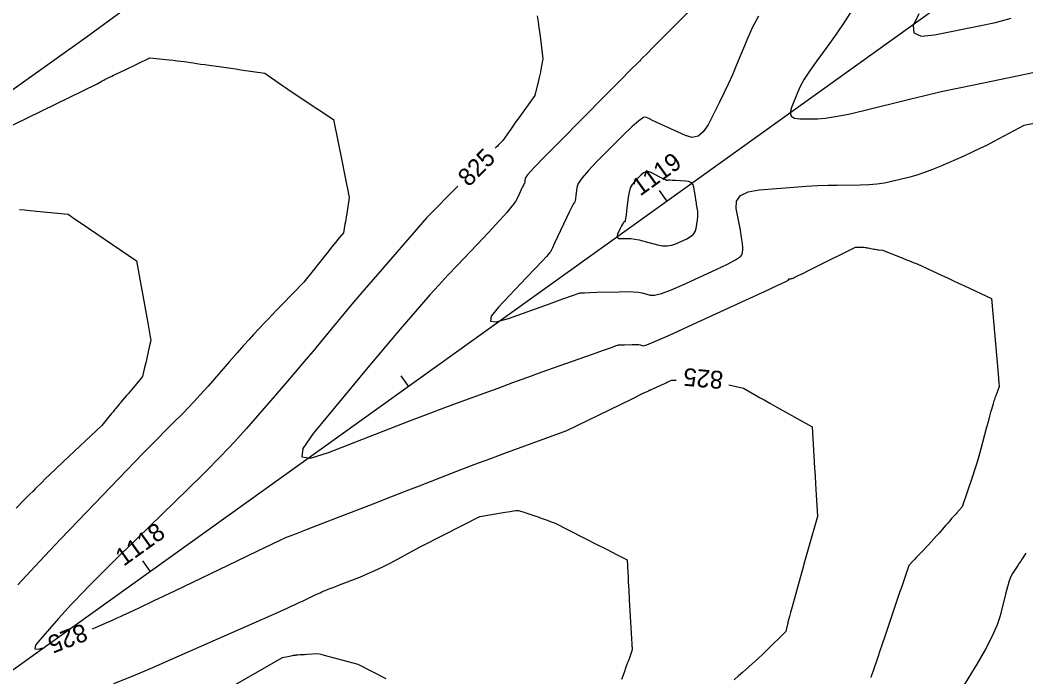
# Model space of a CAD drawing. Extents: x 2079879 to 2092887, y 778083 to 784051.
# Drawn here: x 2083804.7 to 2083962.9, y 780863.7 to 780967 of the extents above; entities that cross this region are included whole.
import ezdxf

# ---------------------------------------------------------------- set-up
doc = ezdxf.new("R2010")
doc.units = 0
for name, color, linetype in [('DT_X_Contour_Major', 7, 'Continuous'), ('DT_X_Contour_Minor', 7, 'Continuous'), ('DT_X_TIN_Hull', 7, 'Continuous'), ('GE_X_CL_20', 7, 'Continuous')]:
    doc.layers.add(name, color=color, linetype=linetype)

msp = doc.modelspace()

# ---------------------------------------------------------------- linework, layer by layer
at = {"layer": 'DT_X_Contour_Major'}
for points in [[(2083886.06, 780967.74), (2083886.19, 780966.75), (2083886.32, 780965.81), (2083886.43, 780964.93), (2083886.94, 780960.96), (2083886.62, 780959.26), (2083886.54, 780958.88), (2083886.46, 780958.46), (2083886.35, 780958.01), (2083886.24, 780957.52), (2083885.68, 780955.17), (2083883.14, 780951.66), (2083882.64, 780950.97), (2083882.22, 780950.38), (2083881.88, 780949.91), (2083881.63, 780949.54), (2083880.62, 780948.09), (2083879.94, 780947.41), (2083879.78, 780947.24), (2083879.59, 780947.05), (2083879.45, 780946.91)], [(2083873.55, 780940.93), (2083868.66, 780935.98), (2083860.21, 780926.23), (2083858.47, 780924.22), (2083856.87, 780922.34), (2083855.4, 780920.6), (2083854.08, 780919), (2083850.72, 780914.93), (2083849.4, 780913.35), (2083847.98, 780911.67), (2083846.46, 780909.89), (2083844.82, 780908), (2083840.31, 780902.83), (2083838.46, 780900.78), (2083836.29, 780898.48), (2083833.8, 780895.95), (2083830.99, 780893.18), (2083823.07, 780885.47), (2083820.39, 780882.86), (2083818.3, 780880.81), (2083816.79, 780879.32), (2083815.87, 780878.38), (2083814.18, 780876.64), (2083813.49, 780875.92), (2083812.69, 780875.05), (2083811.78, 780874.05), (2083810.75, 780872.91), (2083807.87, 780869.69), (2083807.11, 780868.7), (2083807.01, 780868.17), (2083807.56, 780868.09), (2083808.22, 780868.29)], [(2083816.05, 780871.31), (2083816.55, 780871.51), (2083817.37, 780871.87), (2083819.3, 780872.72), (2083819.95, 780873.01), (2083820.46, 780873.23), (2083821.02, 780873.48), (2083821.38, 780873.64), (2083821.96, 780873.91), (2083823.43, 780874.61), (2083825.78, 780875.74), (2083829.02, 780877.29), (2083838.85, 780882.01), (2083842.08, 780883.56), (2083844.39, 780884.67), (2083845.8, 780885.34), (2083846.28, 780885.57), (2083846.36, 780885.61), (2083846.76, 780885.76), (2083847.89, 780886.2), (2083849.75, 780886.92), (2083852.34, 780887.92), (2083860.23, 780890.97), (2083863.01, 780892.04), (2083865.44, 780892.99), (2083867.52, 780893.79), (2083869.26, 780894.47), (2083873.41, 780896.09), (2083875.04, 780896.71), (2083876.81, 780897.39), (2083878.73, 780898.1), (2083880.78, 780898.86), (2083890.7, 780902.49), (2083899.17, 780906.6), (2083900.78, 780907.38), (2083902.74, 780908.34), (2083903.1, 780908.51), (2083903.49, 780908.7), (2083903.62, 780908.76), (2083903.71, 780908.81), (2083903.79, 780908.85), (2083903.81, 780908.85), (2083903.86, 780908.88), (2083903.99, 780908.94), (2083904.22, 780909.04), (2083905.51, 780909.62), (2083905.84, 780909.77), (2083906.12, 780909.9), (2083906.34, 780910), (2083906.51, 780910.08), (2083907.16, 780910.4), (2083907.89, 780910.41), (2083907.93, 780910.41)], [(2083916.2, 780909.67), (2083918.5, 780909.14), (2083920.51, 780908), (2083921.03, 780907.7), (2083921.75, 780907.3), (2083922.66, 780906.79), (2083923.76, 780906.17), (2083929.33, 780903.05), (2083929.69, 780896.62), (2083929.76, 780895.32), (2083929.82, 780894.18), (2083929.88, 780893.2), (2083929.93, 780892.39), (2083930.16, 780888.94), (2083928.74, 780884.04), (2083928.43, 780882.96), (2083928.11, 780881.81), (2083927.77, 780880.61), (2083927.42, 780879.34), (2083926.48, 780875.89), (2083926.16, 780874.73), (2083925.92, 780873.84), (2083925.75, 780873.23), (2083925.65, 780872.89), (2083925.5, 780872.34), (2083925.45, 780872.14), (2083925.4, 780871.96), (2083925.36, 780871.78), (2083925.32, 780871.62), (2083925.15, 780870.89), (2083922.05, 780867.83), (2083921.42, 780867.21), (2083920.85, 780866.66), (2083920.34, 780866.19), (2083919.89, 780865.79), (2083918.79, 780864.82), (2083918.32, 780864.41), (2083917.72, 780863.88), (2083917.01, 780863.26)]]:
    msp.add_lwpolyline(points, dxfattribs=at)
at = {"layer": 'DT_X_Contour_Minor'}
for points in [[(2083913.36, 780971.98), (2083906.42, 780964.93), (2083905.09, 780963.59), (2083904.1, 780962.59), (2083903.44, 780961.92), (2083903.11, 780961.58), (2083902.68, 780961.14), (2083902.53, 780960.99), (2083902.42, 780960.88), (2083902.35, 780960.79), (2083902.31, 780960.74), (2083902.26, 780960.64), (2083902.25, 780960.61), (2083902.23, 780960.59), (2083902.22, 780960.58), (2083902.21, 780960.58), (2083902.18, 780960.59), (2083902.17, 780960.59), (2083902.16, 780960.6), (2083902.16, 780960.6), (2083902.15, 780960.6), (2083901.81, 780960.26), (2083900.8, 780959.25), (2083899.12, 780957.56), (2083896.76, 780955.19), (2083889.58, 780947.97), (2083887.22, 780945.57), (2083885.53, 780943.81), (2083884.51, 780942.69), (2083884.15, 780942.19), (2083884.1, 780941.72), (2083884.08, 780941.57), (2083884.06, 780941.45), (2083884.05, 780941.38), (2083884.03, 780941.35), (2083883.99, 780941.32), (2083883.96, 780941.26), (2083883.88, 780941.1), (2083883.75, 780940.84), (2083883.59, 780940.48), (2083883.08, 780939.4), (2083882.91, 780939.04), (2083882.79, 780938.79), (2083882.71, 780938.63), (2083882.67, 780938.56), (2083882.65, 780938.53), (2083882.6, 780938.47), (2083882.29, 780938.09), (2083882.03, 780937.77), (2083881.24, 780936.8), (2083880.79, 780936.27), (2083880.03, 780935.44), (2083878.96, 780934.29), (2083877.57, 780932.82), (2083873.48, 780928.5), (2083871.97, 780926.9), (2083870.54, 780925.34), (2083869.16, 780923.81), (2083867.86, 780922.33), (2083864.47, 780918.41), (2083863.06, 780916.77), (2083861.37, 780914.77), (2083859.41, 780912.41), (2083857.16, 780909.7), (2083850.81, 780902), (2083849.18, 780899.65), (2083849.03, 780898.37), (2083850.38, 780898.16), (2083853.22, 780899.02), (2083862.77, 780902.74), (2083866.13, 780904.04), (2083869.04, 780905.16), (2083871.5, 780906.09), (2083873.5, 780906.83), (2083878.26, 780908.57), (2083879.89, 780909.17), (2083882.23, 780910.03), (2083882.94, 780910.29), (2083884.42, 780910.83), (2083885.16, 780911.1), (2083886.25, 780911.49), (2083887.69, 780912.01), (2083889.49, 780912.64), (2083894.75, 780914.52), (2083896.48, 780915.13), (2083897.73, 780915.57), (2083898.48, 780915.84), (2083898.74, 780915.94), (2083898.79, 780915.96), (2083898.87, 780915.96), (2083899.05, 780915.97), (2083899.35, 780915.98), (2083899.76, 780915.99), (2083900.99, 780916.03), (2083901.41, 780916.03), (2083901.77, 780916.02), (2083902.05, 780916), (2083902.26, 780915.96), (2083902.72, 780915.83), (2083903.29, 780915.99), (2083904.66, 780916.54), (2083906.84, 780917.5), (2083909.82, 780918.85), (2083918.82, 780923), (2083921.78, 780924.37), (2083923.89, 780925.34), (2083925.15, 780925.93), (2083925.58, 780926.13), (2083925.58, 780926.14), (2083925.58, 780926.15), (2083925.58, 780926.16), (2083925.57, 780926.18), (2083925.57, 780926.2), (2083925.56, 780926.28), (2083925.56, 780926.3), (2083925.59, 780926.32), (2083925.64, 780926.33), (2083925.72, 780926.34), (2083925.95, 780926.36), (2083926.04, 780926.38), (2083926.16, 780926.41), (2083926.29, 780926.47), (2083926.45, 780926.54), (2083926.89, 780926.76), (2083927.21, 780926.91), (2083927.81, 780927.21), (2083928.71, 780927.65), (2083929.9, 780928.24), (2083936.14, 780931.33), (2083936.97, 780931.34), (2083937.14, 780931.34), (2083937.28, 780931.33), (2083937.39, 780931.33), (2083937.48, 780931.31), (2083937.69, 780931.27), (2083937.79, 780931.26), (2083937.93, 780931.23), (2083938.11, 780931.2), (2083938.34, 780931.15), (2083939.01, 780931.04), (2083939.24, 780930.99), (2083939.45, 780930.96), (2083939.62, 780930.93), (2083939.77, 780930.92), (2083940.38, 780930.85), (2083943.55, 780929.59), (2083944.16, 780929.34), (2083944.63, 780929.16), (2083944.97, 780929.02), (2083945.17, 780928.94), (2083945.8, 780928.7), (2083949.74, 780926.89), (2083950.59, 780926.49), (2083951.46, 780926.09), (2083952.35, 780925.68), (2083953.25, 780925.25), (2083957.51, 780923.25), (2083958.34, 780913.74), (2083958.5, 780911.96), (2083958.61, 780910.67), (2083958.68, 780909.88), (2083958.71, 780909.59), (2083958.71, 780909.41), (2083958.18, 780907.95), (2083958.07, 780907.63), (2083957.97, 780907.32), (2083957.86, 780907), (2083957.76, 780906.67), (2083957.51, 780905.8), (2083957.38, 780905.37), (2083957.2, 780904.72), (2083956.97, 780903.86), (2083956.68, 780902.78), (2083955.85, 780899.63), (2083955.53, 780898.46), (2083955.2, 780897.34), (2083954.87, 780896.26), (2083954.53, 780895.23), (2083952.93, 780890.51), (2083952.06, 780889.53), (2083951.89, 780889.33), (2083951.74, 780889.16), (2083951.61, 780889.02), (2083951.5, 780888.9), (2083951.25, 780888.63), (2083951.12, 780888.48), (2083950.91, 780888.25), (2083950.64, 780887.93), (2083950.29, 780887.53), (2083949.26, 780886.35), (2083948.86, 780885.91), (2083948.46, 780885.46), (2083948.04, 780885), (2083947.6, 780884.53), (2083946.43, 780883.29), (2083946.02, 780882.86), (2083945.69, 780882.5), (2083945.43, 780882.22), (2083945.24, 780882.02), (2083944.51, 780881.24), (2083943.35, 780877.82), (2083943.07, 780877.01), (2083942.75, 780876.05), (2083942.37, 780874.94), (2083941.94, 780873.68), (2083940.74, 780870.11), (2083940.32, 780868.88), (2083939.97, 780867.85), (2083939.69, 780867.02), (2083939.47, 780866.39), (2083939, 780865), (2083938.83, 780864.52), (2083938.7, 780864.13), (2083938.6, 780863.83), (2083938.52, 780863.62)], [(2083935.91, 780969.12), (2083934.37, 780966.77), (2083933.08, 780964.85), (2083932.04, 780963.39), (2083929.61, 780960.07), (2083928.77, 780958.86), (2083928.06, 780957.74), (2083927.48, 780956.71), (2083927.04, 780955.75), (2083926.05, 780953.32), (2083925.86, 780952.52), (2083926.01, 780951.95), (2083926.52, 780951.61), (2083927.37, 780951.51), (2083930.12, 780951.52), (2083931.35, 780951.61), (2083932.98, 780951.86), (2083935, 780952.27), (2083937.42, 780952.83), (2083944.4, 780954.57), (2083947.01, 780955.2), (2083949.6, 780955.8), (2083952.18, 780956.36), (2083954.75, 780956.89), (2083961.57, 780958.26), (2083964, 780958.78)], [(2083920.87, 780967.67), (2083919.91, 780965.92), (2083919.16, 780964.27), (2083917.42, 780960.02), (2083916.77, 780958.46), (2083916.11, 780956.96), (2083915.43, 780955.53), (2083914.75, 780954.15), (2083912.92, 780950.57), (2083912.18, 780949.45), (2083911.35, 780948.8), (2083910.42, 780948.6), (2083909.39, 780948.87), (2083906.51, 780950.19), (2083905.53, 780950.64), (2083904.76, 780950.99), (2083904.2, 780951.26), (2083903.84, 780951.44), (2083903.16, 780951.78), (2083902.75, 780951.7), (2083902.01, 780951.2), (2083900.95, 780950.28), (2083899.57, 780948.94), (2083895.45, 780944.8), (2083894.1, 780943.38), (2083893.11, 780942.23), (2083892.5, 780941.33), (2083892.26, 780940.71), (2083892.1, 780939.39), (2083892.05, 780938.96), (2083892, 780938.64), (2083891.95, 780938.43), (2083891.91, 780938.35), (2083891.81, 780938.26), (2083891.71, 780938.09), (2083891.49, 780937.65), (2083891.14, 780936.93), (2083890.67, 780935.94), (2083889.26, 780932.93), (2083888.79, 780931.94), (2083888.46, 780931.23), (2083888.26, 780930.8), (2083888.19, 780930.66), (2083888.18, 780930.65), (2083888.17, 780930.63), (2083888.13, 780930.59), (2083888.08, 780930.52), (2083888, 780930.43), (2083887.77, 780930.15), (2083887.49, 780929.84), (2083886.83, 780929.13), (2083885.77, 780928.01), (2083884.32, 780926.48), (2083879.95, 780921.87), (2083878.82, 780920.46), (2083878.7, 780919.7), (2083879.6, 780919.59), (2083881.51, 780920.13), (2083887.96, 780922.42), (2083890.08, 780923.18), (2083891.59, 780923.71), (2083892.5, 780924.04), (2083892.81, 780924.15), (2083892.83, 780924.15), (2083892.99, 780924.16), (2083893.49, 780924.17), (2083894.31, 780924.2), (2083895.45, 780924.23), (2083898.94, 780924.32), (2083900.15, 780924.33), (2083901.15, 780924.3), (2083901.94, 780924.23), (2083902.54, 780924.12), (2083903.84, 780923.77), (2083904.52, 780923.77), (2083905.58, 780924.03), (2083907.03, 780924.56), (2083908.85, 780925.36), (2083914.21, 780927.83), (2083915.98, 780928.68), (2083917.25, 780929.35), (2083918.03, 780929.86), (2083918.31, 780930.2), (2083918.41, 780930.89), (2083918.41, 780931.28), (2083918.35, 780931.92), (2083918.21, 780932.83), (2083918.01, 780933.99), (2083917.37, 780937.43), (2083917.42, 780938.58), (2083918.04, 780939.45), (2083919.22, 780940.04), (2083920.97, 780940.34), (2083926.41, 780940.77), (2083928.37, 780940.91), (2083930.15, 780941.01), (2083931.77, 780941.08), (2083933.23, 780941.1), (2083936.88, 780941.13), (2083938.21, 780941.17), (2083939.48, 780941.27), (2083940.68, 780941.45), (2083941.81, 780941.69), (2083944.72, 780942.41), (2083945.85, 780942.72), (2083947.04, 780943.11), (2083948.3, 780943.59), (2083949.62, 780944.14), (2083953.23, 780945.72), (2083954.54, 780946.31), (2083955.76, 780946.88), (2083956.9, 780947.44), (2083957.95, 780947.99), (2083962.64, 780950.52), (2083967.45, 780951.47)], [(2083946.07, 780968.04), (2083945.19, 780966.19), (2083945.31, 780965.02), (2083946.43, 780964.53), (2083948.55, 780964.72), (2083955.56, 780966.12), (2083958.13, 780966.69), (2083960.61, 780967.35)], [(2083799.33, 780948.51), (2083816.79, 780957), (2083817.45, 780957.4), (2083817.58, 780957.47), (2083817.69, 780957.54), (2083817.78, 780957.59), (2083817.85, 780957.62), (2083818, 780957.7), (2083818.08, 780957.73), (2083818.2, 780957.79), (2083818.35, 780957.86), (2083818.54, 780957.95), (2083819.11, 780958.22), (2083819.4, 780958.36), (2083819.85, 780958.57), (2083820.45, 780958.86), (2083821.21, 780959.22), (2083825.12, 780961.09), (2083828.14, 780960.8), (2083828.77, 780960.73), (2083829.37, 780960.66), (2083829.95, 780960.59), (2083830.49, 780960.51), (2083831.91, 780960.3), (2083832.47, 780960.22), (2083833.07, 780960.13), (2083833.73, 780960.04), (2083834.43, 780959.94), (2083836.35, 780959.68), (2083837.09, 780959.58), (2083837.84, 780959.47), (2083838.62, 780959.36), (2083839.42, 780959.24), (2083843.21, 780958.68), (2083845.82, 780956.85), (2083846.44, 780956.42), (2083847.19, 780955.91), (2083848.06, 780955.33), (2083849.05, 780954.67), (2083853.98, 780951.41), (2083855.4, 780944.44), (2083855.67, 780943.09), (2083855.89, 780942.03), (2083856.04, 780941.25), (2083856.15, 780940.76), (2083856.48, 780939.13), (2083856.08, 780936.63), (2083856, 780936.12), (2083855.93, 780935.67), (2083855.86, 780935.29), (2083855.8, 780934.97), (2083855.55, 780933.61), (2083854.9, 780932.82), (2083854.68, 780932.54), (2083854.29, 780932.06), (2083853.75, 780931.38), (2083853.03, 780930.49), (2083849.33, 780925.84), (2083845.81, 780922.22), (2083845.07, 780921.46), (2083844.37, 780920.73), (2083843.7, 780920.03), (2083843.07, 780919.35), (2083841.42, 780917.59), (2083840.72, 780916.83), (2083839.85, 780915.87), (2083838.83, 780914.72), (2083837.65, 780913.36), (2083834.27, 780909.49), (2083833.08, 780908.14), (2083832.04, 780906.99), (2083831.14, 780906.04), (2083830.4, 780905.28), (2083828.61, 780903.55), (2083827.67, 780902.6), (2083826.17, 780901.08), (2083824.11, 780898.96), (2083821.5, 780896.26), (2083813.8, 780888.29), (2083811.05, 780885.41), (2083808.55, 780882.77), (2083806.32, 780880.37), (2083804.35, 780878.2)], [(2083909.61, 780932.66), (2083910.18, 780932.99), (2083910.62, 780933.36), (2083910.91, 780933.79), (2083911.05, 780934.28), (2083911.24, 780935.64), (2083911.3, 780936.12), (2083911.33, 780936.55), (2083911.32, 780936.93), (2083911.28, 780937.25), (2083911.13, 780938.05), (2083911.08, 780938.31), (2083911.05, 780938.5), (2083911.03, 780938.62), (2083911.02, 780938.66), (2083911.02, 780938.67), (2083911.02, 780938.73), (2083910.99, 780938.9), (2083910.95, 780939.18), (2083910.89, 780939.57), (2083910.71, 780940.76), (2083910.58, 780941.16), (2083910.31, 780941.45), (2083909.91, 780941.64), (2083909.39, 780941.72), (2083907.8, 780941.81), (2083907.28, 780941.84), (2083906.91, 780941.86), (2083906.69, 780941.87), (2083906.61, 780941.86), (2083906.61, 780941.84), (2083906.61, 780941.83), (2083906.61, 780941.83), (2083906.6, 780941.83), (2083906.58, 780941.83), (2083906.54, 780941.83), (2083906.52, 780941.83), (2083906.5, 780941.84), (2083906.48, 780941.84), (2083906.46, 780941.84), (2083906.39, 780941.86), (2083906.37, 780941.86), (2083906.35, 780941.87), (2083906.33, 780941.87), (2083906.32, 780941.87), (2083906.3, 780941.88), (2083906.24, 780941.91), (2083906.06, 780942), (2083905.76, 780942.15), (2083905.35, 780942.36), (2083904.1, 780943), (2083903.64, 780943.16), (2083903.2, 780943.16), (2083902.78, 780943), (2083902.37, 780942.68), (2083901.33, 780941.63), (2083900.97, 780941.19), (2083900.69, 780940.64), (2083900.49, 780939.98), (2083900.36, 780939.22), (2083900.11, 780937.07), (2083900.02, 780936.35), (2083899.94, 780935.83), (2083899.86, 780935.49), (2083899.8, 780935.34), (2083899.63, 780935.21), (2083899.55, 780935.12), (2083899.45, 780934.95), (2083899.32, 780934.7), (2083899.16, 780934.37), (2083898.69, 780933.38), (2083898.6, 780933.06), (2083898.65, 780932.84), (2083898.85, 780932.7), (2083899.2, 780932.67), (2083900.35, 780932.7), (2083900.82, 780932.68), (2083901.39, 780932.61), (2083902.06, 780932.47), (2083902.82, 780932.28), (2083904.97, 780931.7), (2083905.76, 780931.55), (2083906.5, 780931.53), (2083907.21, 780931.63), (2083907.88, 780931.86), (2083909.61, 780932.66)], [(2083804.59, 780937.24), (2083805.37, 780937.18), (2083806.27, 780937.1), (2083807.27, 780937), (2083812.24, 780936.5), (2083813.42, 780935.69), (2083813.82, 780935.42), (2083815.43, 780934.32), (2083823.01, 780929.17), (2083824.83, 780919.11), (2083825.17, 780917.25), (2083825.22, 780916.98), (2083825.26, 780916.76), (2083825.26, 780916.75), (2083825.26, 780916.75), (2083825.25, 780916.74), (2083825.25, 780916.71), (2083825.23, 780916.63), (2083825.11, 780916.08), (2083825, 780915.59), (2083824.67, 780914.12), (2083824.56, 780913.6), (2083824.45, 780913.14), (2083824.36, 780912.75), (2083824.28, 780912.41), (2083823.93, 780910.99), (2083822.51, 780909.26), (2083822.22, 780908.91), (2083821.94, 780908.58), (2083821.68, 780908.27), (2083821.44, 780907.99), (2083820.82, 780907.27), (2083820.61, 780907.02), (2083820.42, 780906.8), (2083820.27, 780906.62), (2083820.15, 780906.48), (2083819.87, 780906.13), (2083819.74, 780905.97), (2083819.56, 780905.74), (2083819.32, 780905.45), (2083819.02, 780905.09), (2083817.52, 780903.28), (2083811.5, 780897.6), (2083810.32, 780896.48), (2083809.36, 780895.57), (2083808.63, 780894.87), (2083808.13, 780894.38), (2083807.07, 780893.33), (2083806.67, 780892.92), (2083806.24, 780892.5), (2083805.8, 780892.04), (2083805.34, 780891.57), (2083804.08, 780890.26)], [(2083819.41, 780862.67), (2083822.19, 780863.81), (2083825.18, 780865.08), (2083828.38, 780866.48), (2083837.21, 780870.37), (2083840.18, 780871.68), (2083844.11, 780873.41), (2083845.07, 780873.83), (2083846.72, 780874.56), (2083847.33, 780874.84), (2083847.96, 780875.12), (2083848.58, 780875.41), (2083849.21, 780875.71), (2083850.89, 780876.52), (2083851.45, 780876.78), (2083851.87, 780876.98), (2083852.15, 780877.11), (2083852.28, 780877.18), (2083852.46, 780877.25), (2083852.67, 780877.33), (2083853.16, 780877.52), (2083853.92, 780877.82), (2083854.96, 780878.22), (2083858.11, 780879.44), (2083859.31, 780879.93), (2083860.52, 780880.46), (2083861.75, 780881.06), (2083863, 780881.7), (2083866.37, 780883.5), (2083867.62, 780884.17), (2083868.87, 780884.83), (2083870.1, 780885.46), (2083871.33, 780886.09), (2083877, 780888.97), (2083881.01, 780889.62), (2083881.77, 780889.75), (2083882.33, 780889.84), (2083882.68, 780889.89), (2083882.83, 780889.91), (2083883.07, 780889.93), (2083883.65, 780889.75), (2083883.8, 780889.71), (2083884.01, 780889.64), (2083884.27, 780889.55), (2083884.59, 780889.44), (2083885.51, 780889.12), (2083885.85, 780889), (2083886.18, 780888.89), (2083886.49, 780888.77), (2083886.8, 780888.66), (2083887.6, 780888.37), (2083887.87, 780888.26), (2083888.1, 780888.18), (2083888.27, 780888.12), (2083888.4, 780888.08), (2083888.88, 780887.92), (2083895.55, 780884.52), (2083896.84, 780883.86), (2083897.83, 780883.35), (2083898.53, 780883), (2083898.95, 780882.79), (2083900.19, 780882.15), (2083900.3, 780880.12), (2083900.33, 780879.53), (2083900.38, 780878.63), (2083900.45, 780877.41), (2083900.53, 780875.88), (2083900.96, 780868.01), (2083900.73, 780867.23), (2083900.67, 780867.07), (2083900.62, 780866.9), (2083900.56, 780866.73), (2083900.5, 780866.57), (2083900.33, 780866.13), (2083900.22, 780865.82), (2083900.01, 780865.25), (2083899.7, 780864.42), (2083899.29, 780863.31)], [(2083962.93, 780883.17), (2083962.34, 780882.28), (2083962.11, 780881.94), (2083961.89, 780881.61), (2083961.66, 780881.27), (2083961.43, 780880.92), (2083960.82, 780880.01), (2083960.58, 780879.54), (2083960.32, 780878.85), (2083960.03, 780877.92), (2083959.73, 780876.75), (2083958.88, 780873.33), (2083958.41, 780871.9), (2083957.64, 780870.15), (2083956.57, 780868.1), (2083955.2, 780865.75), (2083951.14, 780859.06)], [(2083832.19, 780858.87), (2083845.96, 780866.78), (2083847.08, 780867.01), (2083847.3, 780867.06), (2083847.48, 780867.1), (2083847.62, 780867.12), (2083847.72, 780867.14), (2083847.92, 780867.16), (2083848.01, 780867.17), (2083848.11, 780867.18), (2083848.23, 780867.2), (2083848.37, 780867.21), (2083848.75, 780867.24), (2083848.92, 780867.25), (2083849.15, 780867.27), (2083849.44, 780867.28), (2083849.78, 780867.31), (2083851.53, 780867.42), (2083851.98, 780867.3), (2083852.17, 780867.25), (2083852.55, 780867.14), (2083853.12, 780866.99), (2083853.87, 780866.78), (2083857.83, 780865.71), (2083862.23, 780863.49)]]:
    msp.add_lwpolyline(points, dxfattribs=at)
at = {"layer": 'DT_X_TIN_Hull'}
msp.add_lwpolyline([(2084059.54, 781146.11), (2084036.93, 781129.67), (2084013.14, 781112.39), (2083985.88, 781093.51), (2083962.99, 781072.59), (2083938.75, 781056.62), (2083915.71, 781038.8), (2083889.83, 781019.11), (2083858.55, 781008.75), (2083855.92, 781006.71), (2083852.49, 781002.97), (2083838.69, 780981.61), (2083815.06, 780964.33), (2083790.38, 780946.76)], dxfattribs=at)
at = {"layer": 'GE_X_CL_20'}
for p, q in [((2079923.52, 778084.44), (2085691.45, 782217.74)), ((2083906.45, 780938.6), (2083905.28, 780940.23)), ((2083865.81, 780909.48), (2083864.64, 780911.1)), ((2083825.16, 780880.35), (2083824, 780881.98))]:
    msp.add_line(p, q, dxfattribs=at)

# ---------------------------------------------------------------- texts
at = {"layer": 'DT_X_Contour_Major'}
for rotation, p in [(45.3376, (2083875.27, 780940.69)), (174.922, (2083915.4, 780911.79)), (201.1071, (2083814.59, 780872.21))]:
    msp.add_text('825', height=2.8, rotation=rotation, dxfattribs=at).set_placement(p)
at = {"layer": 'GE_X_CL_20'}
for s, p in [('1119', (2083902.23, 780939.27)), ('1118', (2083820.98, 780881.05))]:
    msp.add_text(s, height=2.8, rotation=35.6254, dxfattribs=at).set_placement(p)

doc.saveas('drawing.dxf')
